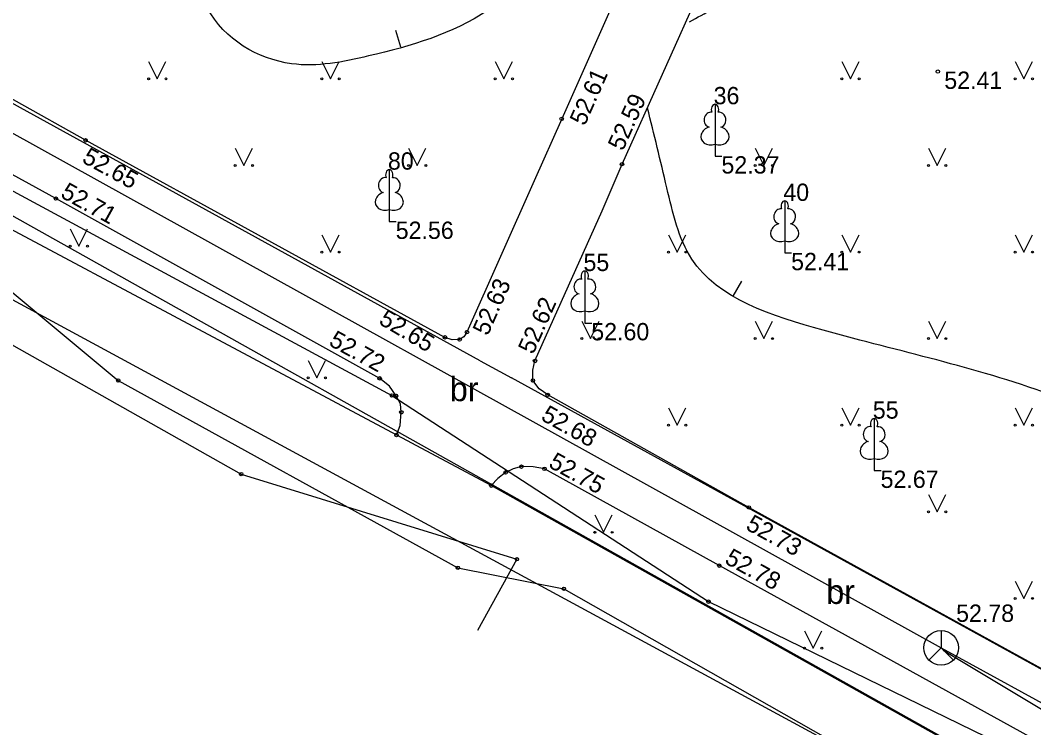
# Model space of a CAD drawing. Extents: x 619806 to 620082, y 405176 to 405386.
# Drawn here: x 619868.55 to 619897.79, y 405248.76 to 405269.19 of the extents above; entities that cross this region are included whole.
import ezdxf

# ---------------------------------------------------------------- set-up
doc = ezdxf.new("R2010")
doc.units = 0
for name, color, linetype in [('24', 7, 'Continuous'), ('APGR_SARK_####_####_#', 7, 'Continuous'), ('APGS_VADP_ZSPR_####_#', 7, 'Continuous'), ('CELI_CMAL_####_####_#', 7, 'Continuous'), ('CELI_CSEG_####_TKST_#', 7, 'Continuous'), ('ELEK_VADP_ZSPR_####_#', 7, 'Continuous'), ('RAMI_UZMR_####_####_#', 7, 'Continuous'), ('RELJ_AATZ_####_TKST_#', 7, 'Continuous'), ('RELJ_ELEM_####_####_#', 7, 'Continuous'), ('RELJ_HORZ_PAMT_####_#', 7, 'Continuous'), ('ROBZ_UZMR_####_####_#', 7, 'Continuous'), ('SAKK_ELEM_####_####_#', 7, 'Continuous'), ('SAKK_ELEM_####_TKST_#', 7, 'Continuous'), ('SAKK_KKAN_####_####_#', 7, 'Continuous'), ('SAKT_VADP_KABE_####_#', 7, 'Continuous'), ('TERT_DIAM_####_TKST_#', 7, 'Continuous'), ('TERT_ELEM_####_####_#', 7, 'Continuous')]:
    doc.layers.add(name, color=color, linetype=linetype)

msp = doc.modelspace()

# ---------------------------------------------------------------- linework, layer by layer
at = {"layer": '24'}
msp.add_line((619881.818, 405259.359), (619882.718, 405258.864), dxfattribs=at)
at = {"layer": 'APGR_SARK_####_####_#'}
msp.add_lwpolyline([(619990.053, 405197.403), (619966.019, 405209.806), (619941.986, 405222.21), (619880.273, 405256.839), (619818.56, 405291.467)], dxfattribs=at)
at = {"layer": 'APGS_VADP_ZSPR_####_#'}
msp.add_lwpolyline([(619827.279, 405290.766), (619828.233, 405290.484), (619831.689, 405284.666), (619835.137, 405280.637), (619844.802, 405275.519), (619857.367, 405269.037), (619864.044, 405264.897), (619871.373, 405258.791), (619881.17, 405253.384), (619884.232, 405252.778), (619898.622, 405244.594), (619910.805, 405239.254), (619917.273, 405236.249), (619923.426, 405231.863), (619936.8, 405224.512), (619938.618, 405223.547), (619972.929, 405204.127)], dxfattribs=at)
at = {"layer": 'CELI_CMAL_####_####_#'}
for points in [[(619899.158, 405249.84), (619889.566, 405255.126), (619883.763, 405258.374), (619883.521, 405258.553), (619883.337, 405258.79), (619883.332, 405259.088), (619883.396, 405259.355), (619885.336, 405263.687), (619885.909, 405265.039), (619889.402, 405272.847), (619890.363, 405275.067), (619891.31, 405274.7), (619892.522, 405277.476), (619891.601, 405277.83), (619893.159, 405281.35), (619896.721, 405289.572), (619907.468, 405289.939)], [(619864.449, 405269.077), (619869.423, 405272.184), (619872.398, 405274.064), (619878.606, 405278.004), (619888.543, 405284.278), (619893.459, 405287.265), (619890.801, 405281.299), (619887.26, 405273.308), (619884.168, 405266.346), (619883.371, 405264.557), (619881.435, 405260.185), (619881.348, 405260.055), (619881.222, 405259.974), (619881.004, 405259.965), (619880.8, 405260.037), (619870.43, 405265.727), (619864.449, 405269.077)], [(619879.4, 405257.217), (619879.508, 405257.489), (619879.539, 405257.873), (619879.512, 405258.12), (619879.389, 405258.35), (619879.204, 405258.631), (619878.916, 405258.852), (619869.574, 405264.043), (619862.595, 405267.872), (619860.859, 405266.8)], [(619919.93, 405234.489), (619920.133, 405234.799), (619920.221, 405235.121), (619920.239, 405235.448), (619920.166, 405235.768), (619920.048, 405236.04), (619919.863, 405236.237), (619908.675, 405242.411), (619898.232, 405248.195), (619888.713, 405253.445), (619883.672, 405256.239), (619883.341, 405256.302), (619883.006, 405256.304), (619882.768, 405256.242), (619882.55, 405256.133), (619882.322, 405255.963), (619882.137, 405255.756)]]:
    msp.add_lwpolyline(points, dxfattribs=at)
at = {"layer": 'ELEK_VADP_ZSPR_####_#'}
for points in [[(619827.133, 405291.802), (619827.743, 405291.898), (619828.762, 405290.038), (619831.425, 405286.162), (619834.68, 405283.716), (619844.517, 405277.484), (619856.454, 405270.832), (619868.451, 405264.196), (619879.269, 405258.357), (619888.402, 405252.405), (619901.725, 405245.908), (619900.354, 405242.567), (619899.734, 405241.465)], [(619827.133, 405291.802), (619827.704, 405291.789), (619828.409, 405290.12), (619829.758, 405288.499), (619829.214, 405285.683), (619831.9, 405284.021), (619834.586, 405281.015), (619842.057, 405276.848), (619851.121, 405270.16), (619862.697, 405262.983), (619874.919, 405256.089), (619882.875, 405253.63), (619881.737, 405251.572)]]:
    msp.add_lwpolyline(points, dxfattribs=at)
at = {"layer": 'RAMI_UZMR_####_####_#'}
msp.add_lwpolyline([(619874.687, 405324.979), (619926.719, 405349.544), (619966.669, 405369.042), (620021.738, 405292.03), (620049.703, 405275.476), (620026.189, 405242.287), (620012.147, 405222.917), (619996.603, 405200.928), (619989.997, 405199.173), (619982.328, 405199.155), (619922.669, 405233.014), (619882.137, 405255.756), (619859.084, 405268.056), (619820.646, 405290.715), (619813.744, 405295.206), (619820.645, 405298.752)], close=True, dxfattribs=at)
at = {"layer": 'RELJ_ELEM_####_####_#'}
for centre in [(619895.021, 405267.711), (619884.168, 405266.346), (619870.43, 405265.727), (619885.909, 405265.039), (619869.574, 405264.043), (619880.8, 405260.037), (619881.435, 405260.185), (619881.222, 405259.974), (619883.396, 405259.355), (619878.916, 405258.852), (619871.373, 405258.791), (619883.337, 405258.79), (619879.269, 405258.357), (619879.389, 405258.35), (619883.763, 405258.374), (619879.539, 405257.873), (619879.4, 405257.217), (619883.006, 405256.304), (619883.672, 405256.239), (619874.919, 405256.089), (619882.55, 405256.133), (619882.137, 405255.756), (619889.566, 405255.126), (619882.875, 405253.63), (619881.17, 405253.384), (619888.713, 405253.445), (619884.232, 405252.778), (619888.402, 405252.405)]:
    msp.add_circle(centre, 0.05, dxfattribs=at)
at = {"layer": 'RELJ_HORZ_PAMT_####_#'}
for p, q in [((619879.376, 405268.905), (619879.521, 405268.426)), ((619889.36, 405261.657), (619889.106, 405261.226))]:
    msp.add_line(p, q, dxfattribs=at)
for points in [[(619887.855, 405269.148), (619889.12, 405269.976), (619890.345, 405272.168), (619891.345, 405274.665), (619892.785, 405275.65), (619894.673, 405276.824), (619895.637, 405278.889), (619895.637, 405282.116), (619896.178, 405285.879), (619897.087, 405286.842), (619898.566, 405288.02), (619902.05, 405287.072), (619905.151, 405285.41), (619906.813, 405285.589), (619908.935, 405287.464), (619909.163, 405286.902), (619908.582, 405283.331), (619907.046, 405271.1), (619905.455, 405265.372), (619902.979, 405260.677), (619900.798, 405257.889), (619898.289, 405258.38), (619891.711, 405260.242), (619887.92, 405262.299), (619887.202, 405264.358), (619886.645, 405266.658)], [(619878.532, 405271.605), (619880.771, 405271.323), (619882.247, 405271.52), (619882.991, 405272.32), (619883.537, 405273.557), (619884.142, 405274.903), (619885.045, 405276.769), (619885.515, 405277.763), (619886.662, 405278.715), (619887.416, 405278.486), (619888.101, 405277.299), (619887.1, 405276.561), (619886.257, 405275.822), (619885.414, 405274.635), (619883.998, 405272.265), (619883.18, 405270.562), (619882.039, 405269.482), (619878.598, 405268.161), (619876.372, 405267.937), (619873.942, 405269.545), (619873.71, 405270.859), (619875.289, 405271.996), (619877.208, 405271.838), (619878.532, 405271.606)]]:
    msp.add_spline(points, degree=3, dxfattribs=at)
at = {"layer": 'ROBZ_UZMR_####_####_#'}
for p, q in [((619881.818, 405259.359), (619864.152, 405269.086)), ((619903.919, 405247.191), (619882.718, 405258.864))]:
    msp.add_line(p, q, dxfattribs=at)
at = {"layer": 'SAKK_ELEM_####_####_#'}
msp.add_line((619895.115, 405251.073), (619895.469, 405250.719), dxfattribs=at)
msp.add_lwpolyline([(619895.115, 405251.573), (619895.115, 405251.073), (619894.761, 405250.719)], dxfattribs=at)
msp.add_circle((619895.115, 405251.073), 0.5, dxfattribs=at)
at = {"layer": 'SAKK_KKAN_####_####_#'}
for points in [[(619816.151, 405294.73), (619816.825, 405294), (619832.922, 405285.576), (619895.115, 405251.073), (619918.714, 405238.138)], [(619895.171, 405251.006), (619903.851, 405245.802), (619901.291, 405240.588)]]:
    msp.add_lwpolyline(points, dxfattribs=at)
at = {"layer": 'SAKT_VADP_KABE_####_#'}
msp.add_lwpolyline([(619817.668, 405301.762), (619818.308, 405291.251), (619820.058, 405288.244), (619821.78, 405286.435), (619865.996, 405262.382), (619894.538, 405246.913), (619928.954, 405228.717), (619988.18, 405195.595)], dxfattribs=at)
at = {"layer": 'TERT_ELEM_####_####_#'}
for p, q in [((619872.25, 405268), (619872.5, 405267.5)), ((619872.5, 405267.5), (619872.75, 405268)), ((619877.25, 405268), (619877.5, 405267.5)), ((619877.5, 405267.5), (619877.75, 405268)), ((619882.25, 405268), (619882.5, 405267.5)), ((619882.5, 405267.5), (619882.75, 405268)), ((619892.25, 405268), (619892.5, 405267.5)), ((619892.5, 405267.5), (619892.75, 405268)), ((619897.25, 405268), (619897.5, 405267.5)), ((619897.5, 405267.5), (619897.75, 405268)), ((619888.591, 405265.614), (619888.591, 405265.267)), ((619874.75, 405265.5), (619875, 405265)), ((619875, 405265), (619875.25, 405265.5)), ((619879.75, 405265.5), (619880, 405265)), ((619880, 405265), (619880.25, 405265.5)), ((619889.75, 405265.5), (619890, 405265)), ((619890, 405265), (619890.25, 405265.5)), ((619894.75, 405265.5), (619895, 405265)), ((619895, 405265), (619895.25, 405265.5)), ((619888.591, 405265.267), (619888.791, 405265.267)), ((619879.193, 405263.726), (619879.193, 405263.379)), ((619879.193, 405263.379), (619879.393, 405263.379)), ((619869.985, 405263.171), (619870.235, 405262.671)), ((619870.235, 405262.671), (619870.485, 405263.171)), ((619877.25, 405263), (619877.5, 405262.5)), ((619877.5, 405262.5), (619877.75, 405263)), ((619887.25, 405263), (619887.5, 405262.5)), ((619887.5, 405262.5), (619887.75, 405263)), ((619892.25, 405263), (619892.5, 405262.5)), ((619892.5, 405262.5), (619892.75, 405263)), ((619897.25, 405263), (619897.5, 405262.5)), ((619897.5, 405262.5), (619897.75, 405263)), ((619890.602, 405262.823), (619890.602, 405262.476)), ((619890.602, 405262.476), (619890.802, 405262.476)), ((619884.835, 405260.798), (619884.835, 405260.451)), ((619884.75, 405260.5), (619885, 405260)), ((619884.835, 405260.451), (619885.035, 405260.451)), ((619885, 405260), (619885.25, 405260.5)), ((619889.75, 405260.5), (619890, 405260)), ((619890, 405260), (619890.25, 405260.5)), ((619894.75, 405260.5), (619895, 405260)), ((619895, 405260), (619895.25, 405260.5)), ((619876.85, 405259.367), (619877.1, 405258.867)), ((619877.1, 405258.867), (619877.35, 405259.367)), ((619887.25, 405258), (619887.5, 405257.5)), ((619887.5, 405257.5), (619887.75, 405258)), ((619892.25, 405258), (619892.5, 405257.5)), ((619892.5, 405257.5), (619892.75, 405258)), ((619897.25, 405258), (619897.5, 405257.5)), ((619897.5, 405257.5), (619897.75, 405258)), ((619893.183, 405256.536), (619893.183, 405256.189)), ((619893.183, 405256.189), (619893.383, 405256.189)), ((619894.75, 405255.5), (619895, 405255)), ((619895, 405255), (619895.25, 405255.5)), ((619885.125, 405254.908), (619885.375, 405254.408)), ((619885.375, 405254.408), (619885.625, 405254.908)), ((619897.25, 405253), (619897.5, 405252.5)), ((619897.5, 405252.5), (619897.75, 405253)), ((619891.173, 405251.561), (619891.423, 405251.061)), ((619891.423, 405251.061), (619891.673, 405251.561))]:
    msp.add_line(p, q, dxfattribs=at)
for points in [[(619888.591, 405266.767), (619888.591, 405265.614)], [(619888.681, 405266.535), (619888.68, 405266.536)], [(619879.193, 405264.879), (619879.193, 405263.726)], [(619879.283, 405264.647), (619879.282, 405264.648)], [(619890.602, 405263.976), (619890.602, 405262.823)], [(619890.692, 405263.744), (619890.691, 405263.745)], [(619884.835, 405261.951), (619884.835, 405260.798)], [(619884.925, 405261.719), (619884.924, 405261.72)], [(619893.183, 405257.689), (619893.183, 405256.536)], [(619893.273, 405257.457), (619893.272, 405257.458)]]:
    msp.add_lwpolyline(points, dxfattribs=at)
for centre, radius in [((619872.25, 405267.5), 0.028), ((619872.75, 405267.5), 0.0263), ((619877.25, 405267.5), 0.028), ((619877.75, 405267.5), 0.0263), ((619882.25, 405267.5), 0.028), ((619882.75, 405267.5), 0.0263), ((619892.25, 405267.5), 0.028), ((619892.75, 405267.5), 0.0263), ((619897.25, 405267.5), 0.028), ((619897.75, 405267.5), 0.0263), ((619874.75, 405265), 0.028), ((619875.25, 405265), 0.0263), ((619879.75, 405265), 0.028), ((619880.25, 405265), 0.0263), ((619889.75, 405265), 0.028), ((619890.25, 405265), 0.0263), ((619894.75, 405265), 0.028), ((619895.25, 405265), 0.0263), ((619869.984, 405262.67), 0.028), ((619870.484, 405262.67), 0.0263), ((619877.25, 405262.5), 0.028), ((619877.75, 405262.5), 0.0263), ((619887.25, 405262.5), 0.028), ((619887.75, 405262.5), 0.0263), ((619892.25, 405262.5), 0.028), ((619892.75, 405262.5), 0.0263), ((619897.25, 405262.5), 0.028), ((619897.75, 405262.5), 0.0263), ((619884.75, 405260), 0.028), ((619885.25, 405260), 0.0263), ((619889.75, 405260), 0.028), ((619890.25, 405260), 0.0263), ((619894.75, 405260), 0.028), ((619895.25, 405260), 0.0263), ((619876.85, 405258.866), 0.028), ((619877.35, 405258.866), 0.0263), ((619887.25, 405257.5), 0.028), ((619887.75, 405257.5), 0.0263), ((619892.25, 405257.5), 0.028), ((619892.75, 405257.5), 0.0263), ((619897.25, 405257.5), 0.028), ((619897.75, 405257.5), 0.0263), ((619894.75, 405255), 0.028), ((619895.25, 405255), 0.0263), ((619885.125, 405254.407), 0.028), ((619885.625, 405254.407), 0.0263), ((619897.25, 405252.5), 0.028), ((619897.75, 405252.5), 0.0263), ((619891.173, 405251.06), 0.028), ((619891.673, 405251.06), 0.0263)]:
    msp.add_circle(centre, radius, dxfattribs=at)
for centre, major_axis, ratio, start_param, end_param in [((619888.463, 405266.322), (-0.039, -0.212), 0.861323, 3.141593, 6.283185), ((619888.591, 405266.617), (0, -0.15), 0.707107, 3.14537, 5.287485), ((619888.591, 405266.617), (0, -0.15), 0.707107, 0.995701, 3.137816), ((619888.719, 405266.322), (0.039, -0.212), 0.861323, 0, 3.141593), ((619888.501, 405265.86), (0.307, 0.095), 0.814445, 1.570796, 4.752015), ((619888.681, 405265.86), (-0.307, 0.095), 0.814445, 1.531171, 4.712389), ((619879.193, 405264.729), (0, -0.15), 0.707107, 3.14537, 5.287485), ((619879.193, 405264.729), (0, -0.15), 0.707107, 0.995701, 3.137816), ((619879.065, 405264.434), (-0.039, -0.212), 0.861323, 3.141593, 6.283185), ((619879.321, 405264.434), (0.039, -0.212), 0.861323, 0, 3.141593), ((619879.103, 405263.972), (0.307, 0.095), 0.814445, 1.570796, 4.752015), ((619879.283, 405263.972), (-0.307, 0.095), 0.814445, 1.531171, 4.712389), ((619890.602, 405263.826), (0, -0.15), 0.707107, 3.14537, 5.287485), ((619890.602, 405263.826), (0, -0.15), 0.707107, 0.995701, 3.137816), ((619890.474, 405263.531), (-0.039, -0.212), 0.861323, 3.141593, 6.283185), ((619890.73, 405263.531), (0.039, -0.212), 0.861323, 0, 3.141593), ((619890.512, 405263.069), (0.307, 0.095), 0.814445, 1.570796, 4.752015), ((619890.692, 405263.069), (-0.307, 0.095), 0.814445, 1.531171, 4.712389), ((619884.835, 405261.801), (0, -0.15), 0.707107, 3.14537, 5.287485), ((619884.835, 405261.801), (0, -0.15), 0.707107, 0.995701, 3.137816), ((619884.707, 405261.506), (-0.039, -0.212), 0.861323, 3.141593, 6.283185), ((619884.963, 405261.506), (0.039, -0.212), 0.861323, 0, 3.141593), ((619884.745, 405261.044), (0.307, 0.095), 0.814445, 1.570796, 4.752015), ((619884.925, 405261.044), (-0.307, 0.095), 0.814445, 1.531171, 4.712389), ((619893.055, 405257.244), (-0.039, -0.212), 0.861323, 3.141593, 6.283185), ((619893.183, 405257.539), (0, -0.15), 0.707107, 3.14537, 5.287485), ((619893.183, 405257.539), (0, -0.15), 0.707107, 0.995701, 3.137816), ((619893.311, 405257.244), (0.039, -0.212), 0.861323, 0, 3.141593), ((619893.093, 405256.782), (0.307, 0.095), 0.814445, 1.570796, 4.752015), ((619893.273, 405256.782), (-0.307, 0.095), 0.814445, 1.531171, 4.712389)]:
    msp.add_ellipse(centre, major_axis=major_axis, ratio=ratio, start_param=start_param, end_param=end_param, dxfattribs=at)

# ---------------------------------------------------------------- texts
at = {"layer": 'CELI_CSEG_####_TKST_#'}
for p in [(619880.938, 405258.194), (619891.799, 405252.34)]:
    msp.add_text('br', height=0.7, dxfattribs=at).set_placement(p)
at = {"layer": 'RELJ_AATZ_####_TKST_#'}
for s, rotation, p in [(' 52.61', 66.0528, (619884.757, 405265.951)), (' 52.59', 65.8981, (619885.857, 405265.226)), (' 52.65', 331.2465, (619870.135, 405265.196)), (' 52.71', 330.9407, (619869.515, 405264.188)), (' 52.63', 66.1154, (619881.959, 405259.89)), (' 52.62', 65.8757, (619883.268, 405259.353)), (' 52.65', 329.3586, (619878.7, 405260.537)), (' 52.72', 331.1413, (619877.257, 405259.911)), (' 52.68', 330.7638, (619883.377, 405257.757)), (' 52.75', 331.0024, (619883.597, 405256.395)), (' 52.73', 331.1415, (619889.286, 405254.597)), (' 52.78', 331.122, (619888.678, 405253.619))]:
    msp.add_text(s, height=0.5, rotation=rotation, dxfattribs=at).set_placement(p)
for s, p in [(' 52.41', (619895.021, 405267.211)), (' 52.37', (619888.591, 405264.767)), (' 52.56', (619879.193, 405262.879)), (' 52.41', (619890.602, 405261.976)), (' 52.60', (619884.835, 405259.951)), (' 52.67', (619893.183, 405255.689))]:
    msp.add_text(s, height=0.5, dxfattribs=at).set_placement(p)
at = {"layer": 'SAKK_ELEM_####_TKST_#'}
msp.add_text(' 52.78', height=0.5, dxfattribs=at).set_placement((619895.362, 405251.822))
at = {"layer": 'TERT_DIAM_####_TKST_#'}
for s, p in [(' 36', (619888.366, 405266.767)), (' 80', (619878.968, 405264.879)), (' 40', (619890.377, 405263.976)), (' 55', (619884.61, 405261.951)), (' 55', (619892.958, 405257.689))]:
    msp.add_text(s, height=0.5, dxfattribs=at).set_placement(p)

doc.saveas('drawing.dxf')
